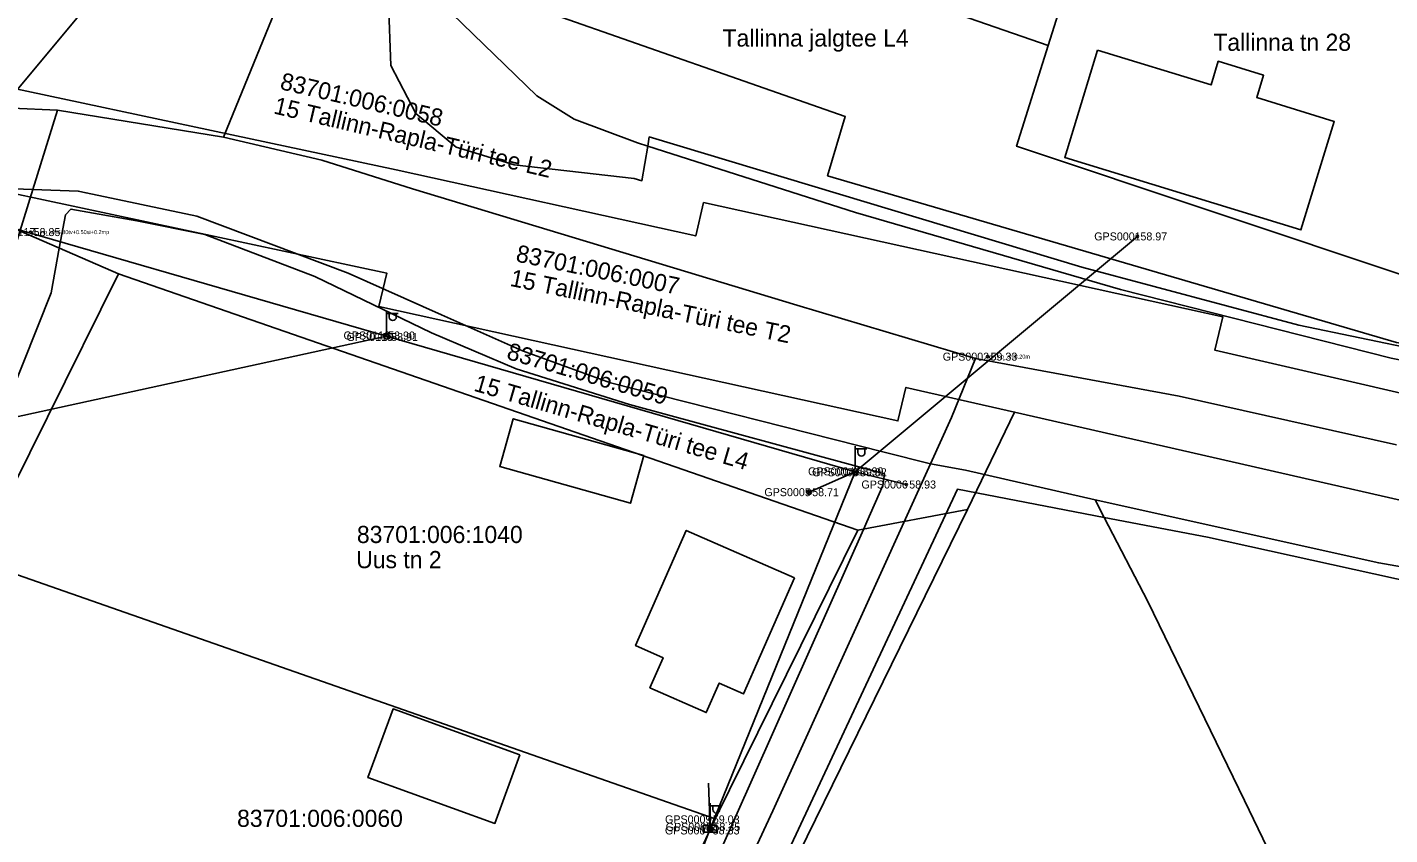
# Model space of a CAD drawing. Extents: x 580119 to 583377, y 6518915 to 6520820.
# Drawn here: x 581868.2 to 581987.4, y 6519691.1 to 6519761.7 of the extents above; entities that cross this region are included whole.
import ezdxf

# ---------------------------------------------------------------- set-up
doc = ezdxf.new("R2010")
doc.units = 0
for name, color, linetype in [('ELRAJATISMP', 7, 'Continuous'), ('Hoone Elu- või ühiskondlik hoone', 7, 'Continuous'), ('Hoone Kõrval- või tootmishoone', 7, 'Continuous'), ('L_AADRESS', 7, 'Continuous'), ('MOOTKORG-EH2000', 7, 'Continuous'), ('MOOTMPUNKT', 7, 'Continuous'), ('MOOTNR', 7, 'Continuous'), ('MPOHULIIN', 7, 'Continuous'), ('PIIR', 7, 'Continuous'), ('POST', 7, 'Continuous'), ('Rippe kõrgus', 7, 'Continuous'), ('Tee Kergliiklustee Püsikate', 7, 'Continuous'), ('Tee Liiklusala', 7, 'Continuous'), ('Tee Rada Kruuskate', 7, 'Continuous'), ('Tee Rada Püsikate', 7, 'Continuous'), ('Tee Tugimaantee Püsikate', 7, 'Continuous'), ('Tee Tänav Püsikate', 7, 'Continuous'), ('TUNNUS', 7, 'Continuous')]:
    doc.layers.add(name, color=color, linetype=linetype)

msp = doc.modelspace()

# ---------------------------------------------------------------- linework, layer by layer
at = {"layer": 'ELRAJATISMP'}
for p, q in [((581927.81, 6519691.9), (581927.81, 6519691.31)), ((581928.08, 6519691.9), (581928.08, 6519691.31))]:
    msp.add_line(p, q, dxfattribs=at)
msp.add_lwpolyline([(581927.35, 6519691.9), (581928.54, 6519691.9), (581928.54, 6519691.31), (581927.35, 6519691.31)], close=True, dxfattribs=at)
at = {"layer": 'Hoone Elu- või ühiskondlik hoone'}
for points in [[(581961.84, 6519759.73), (581971.76, 6519756.68), (581972.39, 6519758.76), (581976.35, 6519757.54), (581975.75, 6519755.58), (581982.54, 6519753.5), (581979.62, 6519744), (581958.96, 6519750.34)], [(581935.33, 6519713.54), (581930.87, 6519703.4), (581928.74, 6519704.34), (581927.61, 6519701.76), (581922.68, 6519703.93), (581923.83, 6519706.56), (581921.43, 6519707.62), (581925.85, 6519717.7)]]:
    msp.add_lwpolyline(points, close=True, dxfattribs=at)
at = {"layer": 'Hoone Kõrval- või tootmishoone'}
for points in [[(581922.14, 6519724.25), (581920.97, 6519720.08), (581909.54, 6519723.3), (581910.72, 6519727.47)], [(581911.31, 6519698.06), (581909.12, 6519692.06), (581898.02, 6519696.08), (581900.21, 6519702.09)]]:
    msp.add_lwpolyline(points, close=True, dxfattribs=at)
at = {"layer": 'MOOTMPUNKT'}
for centre in [(581868.51, 6519743.8), (581965.32, 6519743.43), (581899.52, 6519734.76), (581899.79, 6519734.63), (581952.21, 6519732.91), (581940.5, 6519722.87), (581940.79, 6519722.79), (581936.61, 6519721.05), (581945.1, 6519721.72), (581927.92, 6519692.42), (581927.91, 6519691.45), (581927.98, 6519691.76)]:
    msp.add_circle(centre, 0.1, dxfattribs=at)
at = {"layer": 'MPOHULIIN'}
for p, q in [((581858.9, 6519725.8), (581899.65, 6519734.69)), ((581927.94, 6519691.6), (581927.79, 6519695.58))]:
    msp.add_line(p, q, dxfattribs=at)
for points in [[(581859.1, 6519746.43), (581883.65, 6519775.9), (581910.63, 6519803.45), (581938.38, 6519831.71), (581969.55, 6519863.69), (582004.1, 6519898.63), (582043.97, 6519939.12), (582079.7, 6519981.43), (582116.09, 6520024.19), (582121.9, 6520051.43)], [(581859.1, 6519746.43), (581899.65, 6519734.69), (581940.64, 6519722.83), (581965.32, 6519743.43)], [(581804.37, 6519358.03), (581821.7, 6519394.85), (581841.05, 6519436.04), (581853.88, 6519463.27), (581868.64, 6519494.95), (581880.41, 6519519.75), (581883.7, 6519555), (581891.66, 6519591.76), (581904.02, 6519627.3), (581914.64, 6519657.71), (581927.94, 6519691.6), (581940.64, 6519722.83), (581945.1, 6519721.72)]]:
    msp.add_lwpolyline(points, dxfattribs=at)
at = {"layer": 'PIIR'}
for points in [[(581566.91, 6519916.24), (581765.76, 6519797.71), (581790.19, 6519783.08), (581813.81, 6519771.08), (581830.15, 6519765.04), (581850.62, 6519759.88), (581900.47, 6519749.25), (581926.68, 6519743.47), (581927.37, 6519746.39), (581972.8, 6519736.39), (581972.1, 6519733.47), (582022.4, 6519721.85)], [(582437.14, 6519631.09), (582279.12, 6519665.47), (582181.52, 6519686.86), (582133.4, 6519697.08), (582083.05, 6519708.05), (582033.29, 6519719.34), (582022.4, 6519721.85), (581972.1, 6519733.47), (581972.8, 6519736.39), (581927.37, 6519746.39), (581926.68, 6519743.47), (581900.47, 6519749.25), (581850.62, 6519759.88), (581830.15, 6519765.04), (581813.81, 6519771.08), (581790.19, 6519783.08), (581765.76, 6519797.71), (581566.91, 6519916.24)], [(582014.36, 6519714.4), (581954.58, 6519728.06), (581945.07, 6519730.21), (581944.37, 6519727.29), (581898.97, 6519737.29), (581899.66, 6519740.22), (581848.58, 6519751.11), (581827.48, 6519756.43), (581810.2, 6519762.82), (581785.83, 6519775.2), (581761.13, 6519789.94), (581562.34, 6519908.5)], [(581720.83, 6519828.38), (581751.53, 6519809.56), (581782.73, 6519790.33), (581814.17, 6519771.63), (581824.87, 6519768.18), (581842.25, 6519764.8), (581856.32, 6519767.48), (581864.77, 6519769.48), (581880.15, 6519774.76), (581904.42, 6519766.33), (581939.76, 6519753.92), (581938.22, 6519748.74), (581987.97, 6519734.16), (582025, 6519727.92), (582043.82, 6519724.92), (582041.99, 6519717.52), (582191.36, 6519685.62), (582375.21, 6519645.73)]]:
    msp.add_lwpolyline(points, dxfattribs=at)
for points in [[(581756.15, 6519781.82), (581761.13, 6519789.94), (581785.83, 6519775.2), (581810.2, 6519762.82), (581827.48, 6519756.43), (581848.58, 6519751.11), (581899.66, 6519740.22), (581898.97, 6519737.29), (581944.37, 6519727.29), (581945.07, 6519730.21), (581954.58, 6519728.06), (581950.45, 6519719.52), (581940.85, 6519717.73), (581876.19, 6519740.16), (581862.95, 6519745.89), (581836.27, 6519746.21), (581821.06, 6519746.26), (581818.91, 6519746.03), (581818.63, 6519745.83), (581797.39, 6519753.15), (581799.19, 6519762.22), (581792.48, 6519765.15), (581788.51, 6519764.43)], [(581908.21, 6519777.23), (581910.53, 6519784.06), (581958.73, 6519764.03), (581957.52, 6519760.13)], [(581968.56, 6519783.35), (581973.87, 6519781.29), (582000.11, 6519772.48), (581989.22, 6519739.81), (581954.75, 6519751.32), (581957.52, 6519760.13), (581958.73, 6519764.03)], [(581904.42, 6519766.33), (581908.21, 6519777.23), (581957.52, 6519760.13), (581954.75, 6519751.32), (581989.22, 6519739.81), (581993.48, 6519738.42), (582025, 6519727.92), (581987.97, 6519734.16), (581938.22, 6519748.74), (581939.76, 6519753.92)], [(581862.7, 6519735.58), (581862.95, 6519745.89), (581876.19, 6519740.16), (581863.74, 6519715.07), (581855.33, 6519690.59), (581838.33, 6519642.8), (581821.94, 6519597.83), (581818.32, 6519573.11), (581803.96, 6519517.1), (581795.63, 6519521.82), (581799.07, 6519533.63), (581809.3, 6519578.74), (581818.49, 6519614.04), (581825.04, 6519632.45), (581822.37, 6519633.64), (581830.85, 6519658.81), (581839.33, 6519683.07), (581850.1, 6519715.45), (581851.38, 6519719.23), (581853.38, 6519718.73)], [(581876.19, 6519740.16), (581940.85, 6519717.73), (581928.38, 6519692.46), (581863.74, 6519715.07)], [(581954.58, 6519728.06), (582014.36, 6519714.4), (582011.18, 6519705.55), (581989.6, 6519644.87), (581964.73, 6519654.03), (581925.35, 6519668.32), (581950.45, 6519719.52)], [(581928.38, 6519692.46), (581940.85, 6519717.73), (581950.45, 6519719.52), (581925.35, 6519668.32), (581907.23, 6519615.45), (581892.2, 6519569.11), (581885.44, 6519571.27), (581900.52, 6519618.54), (581916.9, 6519667.86)], [(581863.74, 6519715.07), (581928.38, 6519692.46), (581916.9, 6519667.86), (581855.33, 6519690.59)]]:
    msp.add_lwpolyline(points, close=True, dxfattribs=at)
at = {"layer": 'POST'}
for p, q in [((581899.65, 6519734.94), (581899.65, 6519736.94)), ((581899.65, 6519736.69), (581900.65, 6519736.69)), ((581899.88, 6519736.37), (581899.88, 6519736.69)), ((581900.49, 6519736.37), (581900.49, 6519736.69)), ((581899.65, 6519734.69), (581899.65, 6519734.69)), ((581940.64, 6519723.08), (581940.64, 6519725.08)), ((581940.64, 6519724.83), (581941.64, 6519724.83)), ((581940.87, 6519724.51), (581940.87, 6519724.83)), ((581941.48, 6519724.51), (581941.48, 6519724.83)), ((581940.64, 6519722.83), (581940.64, 6519722.83)), ((581927.94, 6519691.85), (581927.94, 6519693.85)), ((581927.94, 6519693.6), (581928.94, 6519693.6)), ((581928.17, 6519693.28), (581928.17, 6519693.6)), ((581928.78, 6519693.28), (581928.78, 6519693.6)), ((581927.94, 6519691.6), (581927.94, 6519691.6))]:
    msp.add_line(p, q, dxfattribs=at)
msp.add_lwpolyline([(581936.61, 6519721.05), (581940.64, 6519722.83)], dxfattribs=at)
for centre, radius in [((581899.65, 6519734.69), 0.25), ((581940.64, 6519722.83), 0.25), ((581936.61, 6519721.05), 0.2), ((581927.94, 6519691.6), 0.25)]:
    msp.add_circle(centre, radius, dxfattribs=at)
for centre in [(581900.19, 6519736.37), (581941.18, 6519724.51), (581928.48, 6519693.28)]:
    msp.add_arc(centre, 0.306, 180, 0, dxfattribs=at)
at = {"layer": 'Tee Kergliiklustee Püsikate'}
for points in [[(581814.38, 6519755.99), (581827.57, 6519751.09), (581839.67, 6519748.76), (581853.9, 6519748.07), (581868.7, 6519747.53)], [(581868.7, 6519747.53), (581872.68, 6519747.39), (581873.36, 6519747.24), (581883.04, 6519745.2), (581896.29, 6519740.21), (581904.44, 6519736.58), (581911.53, 6519733.42), (581919.22, 6519730.63), (581943.16, 6519724.56), (581947.23, 6519723.53)], [(581947.23, 6519723.53), (581950.29, 6519722.97), (581961.62, 6519720.37)], [(581961.62, 6519720.37), (581986.43, 6519714.86), (582000.47, 6519712.39), (582020.65, 6519709.37), (582034.69, 6519707.15)]]:
    msp.add_lwpolyline(points, dxfattribs=at)
at = {"layer": 'Tee Liiklusala'}
for points in [[(581945.92, 6519829.05), (581913.09, 6519794.59), (581908.31, 6519789.37), (581906.29, 6519785.46), (581903.76, 6519778.95), (581900.68, 6519769.78), (581899.94, 6519764.88), (581899.8, 6519763.92), (581900.03, 6519758.4), (581902.2, 6519754.19), (581905.73, 6519751.23), (581910.81, 6519749.68), (581921.31, 6519748.51), (581921.98, 6519748.3), (581922.49, 6519751.32), (581922.62, 6519752.14), (581960.46, 6519740.75), (581979.43, 6519735.65), (581990.12, 6519733.44), (581991.04, 6519736.96), (582026.29, 6519725.99), (582044.12, 6519722.1)], [(581884.93, 6519570.48), (581907.16, 6519633.3), (581913.91, 6519653.01), (581918.9, 6519667.35), (581941.48, 6519718.06), (581941.65, 6519718.45), (581943.04, 6519721.62), (581943.2, 6519722.65), (581920.89, 6519728.73), (581910.98, 6519731.83), (581903.58, 6519734.98), (581893.37, 6519739.93), (581883.74, 6519743.61), (581877.79, 6519744.78), (581872.03, 6519745.82), (581871.57, 6519745.33), (581871.02, 6519742.4), (581870.3, 6519738.5), (581861.67, 6519716.89)], [(582033.56, 6519705.84), (582020.42, 6519708.13), (581989.7, 6519713.09), (581971.45, 6519717.11), (581962.41, 6519718.84), (581949.57, 6519721.3), (581934.83, 6519689.76), (581924.59, 6519668.45), (581918.69, 6519653.22), (581911.43, 6519632.11), (581903.29, 6519609.3), (581892.83, 6519578.75), (581890.84, 6519572.34), (581890.88, 6519569.49), (581891.63, 6519566.8), (581893.76, 6519564), (581898.15, 6519561.81), (581963.45, 6519544.8), (581972.95, 6519542.2), (581974.27, 6519541.87), (581979.08, 6519540.64)]]:
    msp.add_lwpolyline(points, dxfattribs=at)
at = {"layer": 'Tee Rada Kruuskate'}
msp.add_lwpolyline([(581961.62, 6519720.37), (581962.41, 6519718.84), (581966.22, 6519711.48), (581974.69, 6519694.08), (581985.5, 6519671.64), (581996.32, 6519652.19), (582000.18, 6519645.22), (582003.14, 6519640.3), (582004.45, 6519636.03), (582004.7, 6519632.86)], dxfattribs=at)
at = {"layer": 'Tee Rada Püsikate'}
msp.add_lwpolyline([(581899.94, 6519764.88), (581902.96, 6519764.3), (581905.34, 6519762.93), (581912.78, 6519755.72), (581916.04, 6519753.69), (581921.59, 6519751.61), (581922.49, 6519751.32), (581940.67, 6519745.53), (581963.85, 6519738.78), (581987.52, 6519732.79), (581989.83, 6519732.3)], dxfattribs=at)
at = {"layer": 'Tee Tugimaantee Püsikate'}
for points in [[(581820.98, 6519760.4), (581832.02, 6519757.22), (581846, 6519755.41), (581866.88, 6519754.64), (581870.85, 6519754.49)], [(581870.85, 6519754.49), (581885.37, 6519752.11)], [(581885.37, 6519752.11), (581893.97, 6519750.11), (581901.92, 6519747.59)], [(581901.92, 6519747.59), (581935.52, 6519737.4), (581951.17, 6519732.76)], [(581951.17, 6519732.76), (581968.96, 6519729.46), (581987.99, 6519725.19)]]:
    msp.add_lwpolyline(points, dxfattribs=at)
at = {"layer": 'Tee Tänav Püsikate'}
for points in [[(581893.77, 6519774.39), (581890.16, 6519763.82), (581885.37, 6519752.11)], [(581870.85, 6519754.49), (581868.7, 6519747.53)], [(581868.7, 6519747.53), (581862.94, 6519728.96), (581847.63, 6519684.73), (581827.45, 6519626.92), (581822.87, 6519614.07), (581816.9, 6519592.66), (581815.57, 6519581.17)], [(581949.07, 6519727.58), (581951.17, 6519732.76)], [(581947.23, 6519723.53), (581949.07, 6519727.58)], [(581888.98, 6519560.8), (581887.87, 6519568.35), (581888.02, 6519571.45), (581888.9, 6519574.5), (581904.76, 6519620.34), (581916.99, 6519654.5), (581921.23, 6519666.61), (581925.48, 6519676.03), (581933.43, 6519693.16), (581947.23, 6519723.53)]]:
    msp.add_lwpolyline(points, dxfattribs=at)

# ---------------------------------------------------------------- texts
at = {"layer": 'L_AADRESS'}
for s, p in [('Tallinna jalgtee L4', (581929.03, 6519760.04)), ('Tallinna tn 28', (581971.96, 6519759.67)), ('Uus tn 2', (581896.99, 6519714.4))]:
    msp.add_text(s, height=1.5, dxfattribs=at).set_placement(p)
for s, rotation, p in [('15 Tallinn-Rapla-Türi tee L2', 346.8363, (581889.69, 6519754.2)), ('15 Tallinn-Rapla-Türi tee T2', 348.3541, (581910.37, 6519739.11)), ('15 Tallinn-Rapla-Türi tee L4', 343.7285, (581907.19, 6519729.94))]:
    msp.add_text(s, height=1.5, rotation=rotation, dxfattribs=at).set_placement(p)
at = {"layer": 'MOOTKORG-EH2000'}
for s, p in [(' 58.85', (581868.51, 6519743.46)), (' 58.97', (581965.32, 6519743.08)), (' 58.90', (581899.52, 6519734.41)), (' 58.91', (581899.79, 6519734.28)), (' 59.33', (581952.21, 6519732.56)), (' 58.99', (581940.5, 6519722.52)), (' 59.02', (581940.79, 6519722.44)), (' 58.93', (581945.1, 6519721.37)), (' 58.71', (581936.61, 6519720.7)), (' 59.03', (581927.92, 6519692.07)), (' 58.33', (581927.91, 6519691.1)), (' 58.35', (581927.98, 6519691.41))]:
    msp.add_text(s, height=0.7, dxfattribs=at).set_placement(p)
at = {"layer": 'MOOTNR'}
for s, p in [('GPS0117 ', (581864.87, 6519743.46)), ('GPS0001 ', (581961.54, 6519743.08)), ('GPS0116 ', (581895.88, 6519734.41)), ('GPS0115 ', (581896.15, 6519734.28)), ('GPS0002 ', (581948.29, 6519732.56)), ('GPS0004 ', (581936.51, 6519722.52)), ('GPS0003 ', (581936.87, 6519722.44)), ('GPS0006 ', (581941.18, 6519721.37)), ('GPS0005 ', (581932.69, 6519720.7)), ('GPS0009 ', (581924, 6519692.07)), ('GPS0007 ', (581923.99, 6519691.1)), ('GPS0008 ', (581924.06, 6519691.41))]:
    msp.add_text(s, height=0.7, dxfattribs=at).set_placement(p)
at = {"layer": 'Rippe kõrgus'}
for s, p in [(' el_mp_ohl6.80tv+0.50si+0.2mp', (581868.51, 6519743.63)), (' el_mp_ohl8.20m', (581952.21, 6519732.74))]:
    msp.add_text(s, height=0.35, dxfattribs=at).set_placement(p)
at = {"layer": 'TUNNUS'}
for s, rotation, p in [('83701:006:0058', 346.8363, (581890.25, 6519756.33)), ('83701:006:0007', 348.3541, (581910.88, 6519741.25)), ('83701:006:0059', 343.7285, (581910.06, 6519732.73))]:
    msp.add_text(s, height=1.5, rotation=rotation, dxfattribs=at).set_placement(p)
for s, p in [('83701:006:1040', (581897.05, 6519716.6)), ('83701:006:0060', (581886.57, 6519691.76))]:
    msp.add_text(s, height=1.5, dxfattribs=at).set_placement(p)

doc.saveas('drawing.dxf')
